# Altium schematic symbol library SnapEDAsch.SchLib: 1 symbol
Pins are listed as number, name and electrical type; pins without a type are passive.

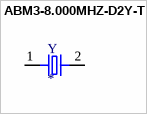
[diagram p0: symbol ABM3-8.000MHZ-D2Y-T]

## ABM3-8.000MHZ-D2Y-T
designator Y
8MHz Â±20ppm Crystal 18pF 140 Ohms 2-SMD, No Lead; MP: ABM3-8.000MHZ-D2Y-T; MF: Abracon
footprint XTAL500X320X130N
pins: 1, 2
